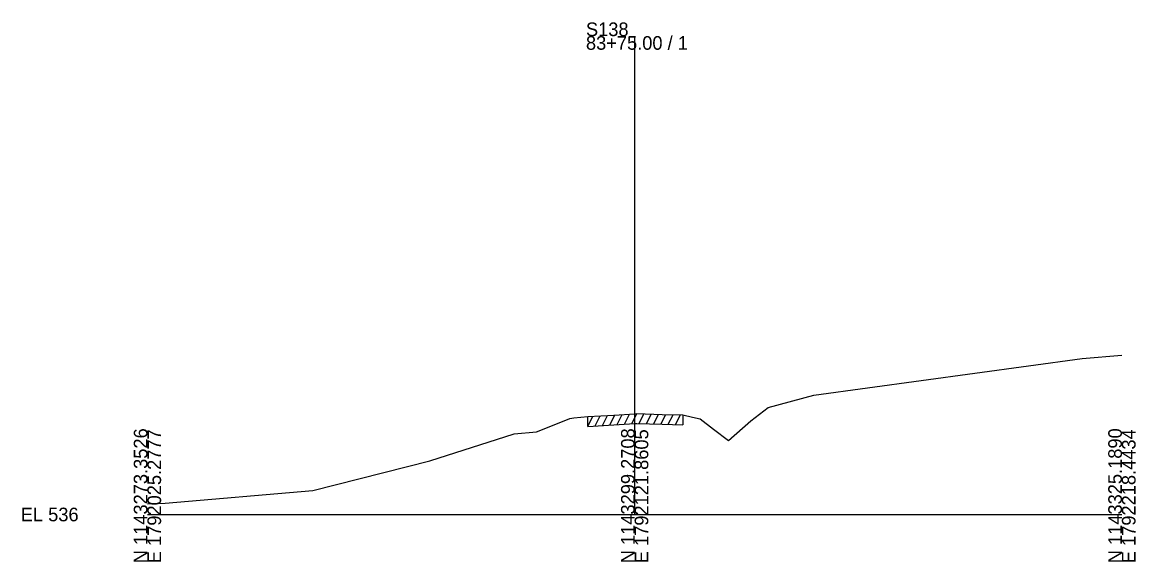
# Model space of a CAD drawing. Extents: x -26 to 1203, y -10 to 19606.
# Drawn here: x -25.7 to 202.8, y 7490.3 to 7601 of the extents above; entities that cross this region are included whole.
import ezdxf

# ---------------------------------------------------------------- set-up
doc = ezdxf.new("R2010")
doc.units = 0
for name, color, linetype in [('RD_EX_Driveway', 7, 'Continuous'), ('RD_GPK_XS_Cell', 7, 'Continuous'), ('RD_XS_ExGround', 7, 'Continuous'), ('RD_XS_ExPaveRet', 7, 'Continuous')]:
    doc.layers.add(name, color=color, linetype=linetype)

msp = doc.modelspace()

# ---------------------------------------------------------------- linework, layer by layer
at = {"layer": 'RD_GPK_XS_Cell'}
for p, q in [((100, 7500), (100, 7598.17)), ((0, 7500), (100, 7500)), ((100, 7500), (200, 7500))]:
    msp.add_line(p, q, dxfattribs=at)
at = {"layer": 'RD_XS_ExGround'}
msp.add_lwpolyline([(0, 7502.21), (3.63, 7502.3), (33.93, 7504.92), (57.97, 7511.03), (75.27, 7516.56), (79.82, 7516.96), (85.87, 7519.37), (86.72, 7519.73), (87.53, 7519.83), (90.4, 7520.09), (95.74, 7520.41), (100, 7520.67), (100.44, 7520.7), (105.63, 7520.55), (109.89, 7520.42), (111.89, 7519.97), (113.47, 7519.6), (116.18, 7517.49), (119.27, 7515.21), (123.86, 7519.24), (127.39, 7521.98), (136.77, 7524.49), (191.86, 7532.01), (200, 7532.72)], dxfattribs=at)
at = {"layer": 'RD_XS_ExPaveRet'}
for p, q in [((90.4, 7518.09), (91.43, 7520.15)), ((90.4, 7518.09), (90.4, 7520.09)), ((91.9, 7518.18), (92.93, 7520.24)), ((93.4, 7518.27), (94.43, 7520.33)), ((94.9, 7518.36), (95.93, 7520.42)), ((96.4, 7518.45), (97.43, 7520.51)), ((97.9, 7518.54), (98.93, 7520.61)), ((99.4, 7518.63), (100.43, 7520.7)), ((100.9, 7518.69), (101.89, 7520.66)), ((102.4, 7518.64), (103.39, 7520.62)), ((103.9, 7518.6), (104.89, 7520.57)), ((105.4, 7518.56), (106.39, 7520.53)), ((106.9, 7518.51), (107.89, 7520.48)), ((108.4, 7518.47), (109.39, 7520.44)), ((109.89, 7520.42), (109.89, 7518.42)), ((90.4, 7518.09), (95.74, 7518.41)), ((95.74, 7518.41), (100, 7518.67)), ((100, 7518.67), (100.44, 7518.7)), ((100.44, 7518.7), (105.63, 7518.55)), ((105.63, 7518.55), (109.89, 7518.42))]:
    msp.add_line(p, q, dxfattribs=at)

# ---------------------------------------------------------------- texts
at = {"layer": 'RD_EX_Driveway'}
msp.add_text('546.34', height=0.0975, rotation=90, dxfattribs=at).set_placement((100.1, 7520.67))
at = {"layer": 'RD_GPK_XS_Cell'}
for s, p in [('S138', (90, 7598.17)), ('83+75.00 / 1', (90, 7595.37)), ('EL 536', (-26, 7498.6))]:
    msp.add_text(s, height=2.8, dxfattribs=at).set_placement(p)
for s, p in [('N 1143273.3526', (0, 7490)), ('E 1792025.2777', (2.8, 7490)), ('N 1143299.2708', (100, 7490)), ('E 1792121.8605', (102.8, 7490)), ('N 1143325.1890', (200, 7490)), ('E 1792218.4434', (202.8, 7490))]:
    msp.add_text(s, height=2.8, rotation=90, dxfattribs=at).set_placement(p)

doc.saveas('drawing.dxf')
